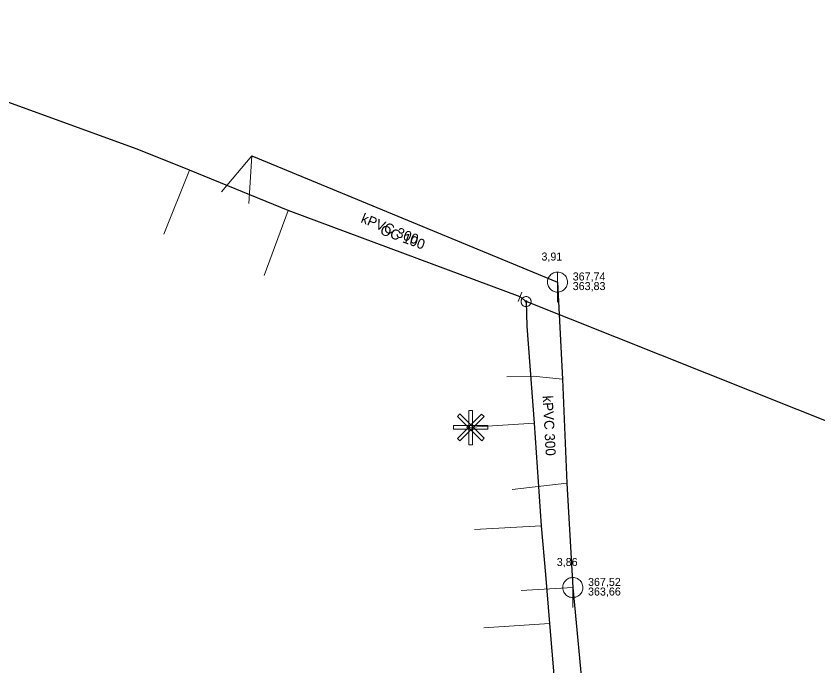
# Model space of a CAD drawing. Extents: x -809916 to -809489, y -991143 to -990912.
# Drawn here: x -809621.9 to -809541.8, y -990985.1 to -990920.2 of the extents above; entities that cross this region are included whole.
import ezdxf

# ---------------------------------------------------------------- set-up
doc = ezdxf.new("R2010")
doc.units = 0
doc.header["$LTSCALE"] = 0.32
doc.layers.add('1', color=7, linetype='Continuous')
for name, color, linetype, lineweight in [('11', 7, 'Continuous', 13), ('12', 7, 'Continuous', 13), ('13', 7, 'Continuous', 13), ('14', 7, 'Continuous', 25), ('17', 7, 'Continuous', 25), ('19', 7, 'Continuous', 13), ('22', 7, 'Continuous', 13), ('34', 7, 'Continuous', 13), ('47', 7, 'Continuous', 13)]:
    doc.layers.add(name, color=color, linetype=linetype, lineweight=lineweight)

msp = doc.modelspace()

# ---------------------------------------------------------------- linework, layer by layer
at = {"layer": '11'}
for p, q in [((-809601.388, -990937.747), (-809598.342, -990934.149)), ((-809598.664, -990938.899), (-809598.342, -990934.149)), ((-809572.339, -990967.454), (-809566.881, -990966.848)), ((-809571.47, -990977.553), (-809566.299, -990977.262))]:
    msp.add_line(p, q, dxfattribs=at)
msp.add_lwpolyline([(-809572.89, -990956.228), (-809570.263, -990956.155), (-809567.318, -990956.434)], dxfattribs=at)
at = {"layer": '12'}
for points in [[(-809576.668, -990959.567), (-809576.318, -990959.567), (-809576.318, -990963.002), (-809576.668, -990963.002)], [(-809575.402, -990959.931), (-809575.154, -990960.179), (-809577.583, -990962.608), (-809577.83, -990962.36)], [(-809577.821, -990960.17), (-809577.574, -990959.922), (-809575.145, -990962.351), (-809575.392, -990962.599)], [(-809574.784, -990961.076), (-809574.784, -990961.426), (-809578.219, -990961.426), (-809578.219, -990961.076)]]:
    msp.add_lwpolyline(points, close=True, dxfattribs=at)
at = {"layer": '13'}
for p, q in [((-809604.59, -990935.56), (-809607.14, -990941.955)), ((-809594.74, -990939.588), (-809597.112, -990946.095)), ((-809570.152, -990960.841), (-809576.906, -990961.279)), ((-809569.461, -990971.101), (-809576.114, -990971.449)), ((-809568.635, -990980.85), (-809575.199, -990981.286))]:
    msp.add_line(p, q, dxfattribs=at)
at = {"layer": '14'}
msp.add_line((-809598.342, -990934.149), (-809567.828, -990946.748), dxfattribs=at)
at = {"layer": '14', "lineweight": 13}
msp.add_line((-809570.963, -990948.696), (-809571.565, -990948.231), dxfattribs=at)
at = {"layer": '14'}
for points in [[(-809567.828, -990946.748), (-809567.318, -990956.434), (-809566.881, -990966.848), (-809566.299, -990977.262)], [(-809566.299, -990977.262), (-809565.206, -990988.914), (-809563.556, -991008.277), (-809561.458, -991027.97)]]:
    msp.add_lwpolyline(points, dxfattribs=at)
at = {"layer": '17'}
for points in [[(-809571.565, -990948.231), (-809594.739, -990939.588), (-809604.59, -990935.559), (-809609.82, -990933.473), (-809622.739, -990928.776), (-809629.397, -990926.193), (-809642.024, -990921.442), (-809644.754, -990920.484), (-809645.469, -990920.17)], [(-809488.614, -990980.461), (-809499.099, -990976.453), (-809528.177, -990965.614), (-809539.454, -990961.256), (-809570.963, -990948.696)], [(-809570.963, -990948.696), (-809570.888, -990951.155), (-809570.151, -990960.84), (-809569.46, -990971.101), (-809569.015, -990975.975), (-809568.635, -990980.85), (-809568.171, -990986.399), (-809566.509, -991011.539)]]:
    msp.add_lwpolyline(points, dxfattribs=at)
at = {"layer": '22'}
for p, q in [((-809567.828, -990948.748), (-809567.827, -990945.748)), ((-809566.299, -990979.262), (-809566.298, -990976.262))]:
    msp.add_line(p, q, dxfattribs=at)
for points in [[(-809566.828, -990946.748), (-809566.833, -990946.639), (-809566.851, -990946.531), (-809566.881, -990946.425), (-809566.921, -990946.324), (-809566.973, -990946.227), (-809567.035, -990946.137), (-809567.107, -990946.054), (-809567.187, -990945.98), (-809567.275, -990945.914), (-809567.369, -990945.859), (-809567.469, -990945.814), (-809567.574, -990945.781), (-809567.681, -990945.759), (-809567.79, -990945.749), (-809567.9, -990945.751), (-809568.008, -990945.765), (-809568.115, -990945.79), (-809568.218, -990945.827), (-809568.316, -990945.876), (-809568.408, -990945.934), (-809568.494, -990946.003), (-809568.571, -990946.08), (-809568.64, -990946.166), (-809568.699, -990946.258), (-809568.747, -990946.356), (-809568.784, -990946.459), (-809568.81, -990946.566), (-809568.824, -990946.674), (-809568.827, -990946.784), (-809568.817, -990946.893), (-809568.796, -990947), (-809568.762, -990947.104), (-809568.718, -990947.204), (-809568.663, -990947.299), (-809568.597, -990947.387), (-809568.523, -990947.467), (-809568.44, -990947.539), (-809568.35, -990947.601), (-809568.254, -990947.653), (-809568.152, -990947.694), (-809568.047, -990947.724), (-809567.939, -990947.742), (-809567.829, -990947.748), (-809567.72, -990947.742), (-809567.612, -990947.724), (-809567.507, -990947.695), (-809567.405, -990947.654), (-809567.308, -990947.602), (-809567.218, -990947.54), (-809567.135, -990947.469), (-809567.06, -990947.389), (-809566.995, -990947.301), (-809566.939, -990947.207), (-809566.895, -990947.107), (-809566.861, -990947.003), (-809566.839, -990946.895), (-809566.829, -990946.786)], [(-809565.299, -990977.262), (-809565.304, -990977.153), (-809565.322, -990977.045), (-809565.352, -990976.939), (-809565.392, -990976.838), (-809565.444, -990976.741), (-809565.506, -990976.651), (-809565.578, -990976.568), (-809565.658, -990976.494), (-809565.746, -990976.428), (-809565.84, -990976.373), (-809565.94, -990976.328), (-809566.045, -990976.295), (-809566.152, -990976.273), (-809566.261, -990976.263), (-809566.371, -990976.265), (-809566.479, -990976.279), (-809566.586, -990976.304), (-809566.689, -990976.341), (-809566.787, -990976.39), (-809566.879, -990976.448), (-809566.965, -990976.517), (-809567.042, -990976.594), (-809567.111, -990976.68), (-809567.17, -990976.772), (-809567.218, -990976.87), (-809567.255, -990976.973), (-809567.281, -990977.08), (-809567.295, -990977.188), (-809567.298, -990977.298), (-809567.288, -990977.407), (-809567.267, -990977.514), (-809567.233, -990977.618), (-809567.189, -990977.718), (-809567.134, -990977.813), (-809567.068, -990977.901), (-809566.994, -990977.981), (-809566.911, -990978.053), (-809566.821, -990978.115), (-809566.725, -990978.167), (-809566.623, -990978.208), (-809566.518, -990978.238), (-809566.41, -990978.256), (-809566.3, -990978.262), (-809566.191, -990978.256), (-809566.083, -990978.238), (-809565.978, -990978.209), (-809565.876, -990978.168), (-809565.779, -990978.116), (-809565.689, -990978.054), (-809565.606, -990977.983), (-809565.531, -990977.903), (-809565.466, -990977.815), (-809565.41, -990977.721), (-809565.366, -990977.621), (-809565.332, -990977.517), (-809565.31, -990977.409), (-809565.3, -990977.3)]]:
    msp.add_lwpolyline(points, close=True, dxfattribs=at)
at = {"layer": '34'}
msp.add_line((-809571.39, -990947.762), (-809571.74, -990948.699), dxfattribs=at)
at = {"layer": '47'}
for points in [[(-809570.498, -990948.881), (-809570.482, -990948.831), (-809570.47, -990948.78), (-809570.464, -990948.728), (-809570.463, -990948.676), (-809570.468, -990948.624), (-809570.478, -990948.572), (-809570.494, -990948.523), (-809570.515, -990948.475), (-809570.54, -990948.429), (-809570.57, -990948.386), (-809570.605, -990948.346), (-809570.644, -990948.311), (-809570.685, -990948.28), (-809570.73, -990948.253), (-809570.777, -990948.231), (-809570.827, -990948.215), (-809570.878, -990948.203), (-809570.931, -990948.197), (-809570.982, -990948.196), (-809571.034, -990948.201), (-809571.086, -990948.211), (-809571.136, -990948.227), (-809571.184, -990948.247), (-809571.23, -990948.272), (-809571.272, -990948.303), (-809571.312, -990948.338), (-809571.348, -990948.376), (-809571.378, -990948.418), (-809571.405, -990948.463), (-809571.427, -990948.51), (-809571.443, -990948.56), (-809571.455, -990948.611), (-809571.462, -990948.663), (-809571.462, -990948.715), (-809571.457, -990948.767), (-809571.448, -990948.819), (-809571.432, -990948.869), (-809571.411, -990948.917), (-809571.386, -990948.963), (-809571.355, -990949.005), (-809571.32, -990949.045), (-809571.283, -990949.08), (-809571.24, -990949.111), (-809571.195, -990949.138), (-809571.148, -990949.16), (-809571.098, -990949.176), (-809571.047, -990949.188), (-809570.996, -990949.195), (-809570.943, -990949.195), (-809570.891, -990949.19), (-809570.839, -990949.181), (-809570.79, -990949.165), (-809570.742, -990949.144), (-809570.696, -990949.118), (-809570.653, -990949.088), (-809570.613, -990949.053), (-809570.579, -990949.015), (-809570.547, -990948.973), (-809570.52, -990948.928)], [(-809570.886, -990948.726), (-809570.883, -990948.718), (-809570.882, -990948.709), (-809570.881, -990948.701), (-809570.881, -990948.693), (-809570.881, -990948.684), (-809570.883, -990948.675), (-809570.885, -990948.667), (-809570.889, -990948.659), (-809570.893, -990948.652), (-809570.898, -990948.645), (-809570.904, -990948.638), (-809570.91, -990948.632), (-809570.917, -990948.627), (-809570.924, -990948.623), (-809570.932, -990948.619), (-809570.94, -990948.616), (-809570.949, -990948.615), (-809570.957, -990948.614), (-809570.965, -990948.614), (-809570.974, -990948.614), (-809570.983, -990948.616), (-809570.991, -990948.618), (-809570.999, -990948.622), (-809571.007, -990948.626), (-809571.013, -990948.631), (-809571.02, -990948.637), (-809571.026, -990948.643), (-809571.031, -990948.65), (-809571.035, -990948.657), (-809571.039, -990948.665), (-809571.042, -990948.673), (-809571.043, -990948.682), (-809571.044, -990948.69), (-809571.044, -990948.698), (-809571.044, -990948.707), (-809571.043, -990948.715), (-809571.04, -990948.724), (-809571.036, -990948.732), (-809571.032, -990948.74), (-809571.027, -990948.746), (-809571.021, -990948.753), (-809571.015, -990948.759), (-809571.008, -990948.764), (-809571.001, -990948.768), (-809570.993, -990948.772), (-809570.985, -990948.775), (-809570.976, -990948.776), (-809570.968, -990948.777), (-809570.96, -990948.777), (-809570.951, -990948.777), (-809570.943, -990948.776), (-809570.934, -990948.773), (-809570.926, -990948.769), (-809570.919, -990948.765), (-809570.912, -990948.76), (-809570.905, -990948.754), (-809570.899, -990948.748), (-809570.894, -990948.741), (-809570.89, -990948.734)]]:
    msp.add_lwpolyline(points, close=True, dxfattribs=at)

# ---------------------------------------------------------------- texts
at = {"layer": '1'}
for s, rotation, p in [('kPVC 300', 338, (-809587.54, -990940.756)), ('OC 100', 340, (-809585.618, -990941.938)), ('kPVC 300', 273, (-809569.307, -990958.112))]:
    msp.add_text(s, height=1, rotation=rotation, dxfattribs=at).set_placement(p)
for s, p in [('3,91', (-809569.428, -990944.596)), ('3,86', (-809567.899, -990975.11))]:
    msp.add_text(s, height=0.8, dxfattribs=at).set_placement(p)
at = {"layer": '19'}
for s, p in [('367,74', (-809566.306, -990946.588)), ('363,83', (-809566.306, -990947.548)), ('367,52', (-809564.777, -990977.102)), ('363,66', (-809564.777, -990978.062))]:
    msp.add_text(s, height=0.8, dxfattribs=at).set_placement(p)

doc.saveas('drawing.dxf')
